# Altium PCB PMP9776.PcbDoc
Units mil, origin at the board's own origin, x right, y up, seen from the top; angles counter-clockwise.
Board outline 1968.5 x 590.55 mil, 2 copper layers (Top Layer, Bottom Layer), stack 62 mil thick; 59 components, 35 nets, 155 pads, 22 vias.
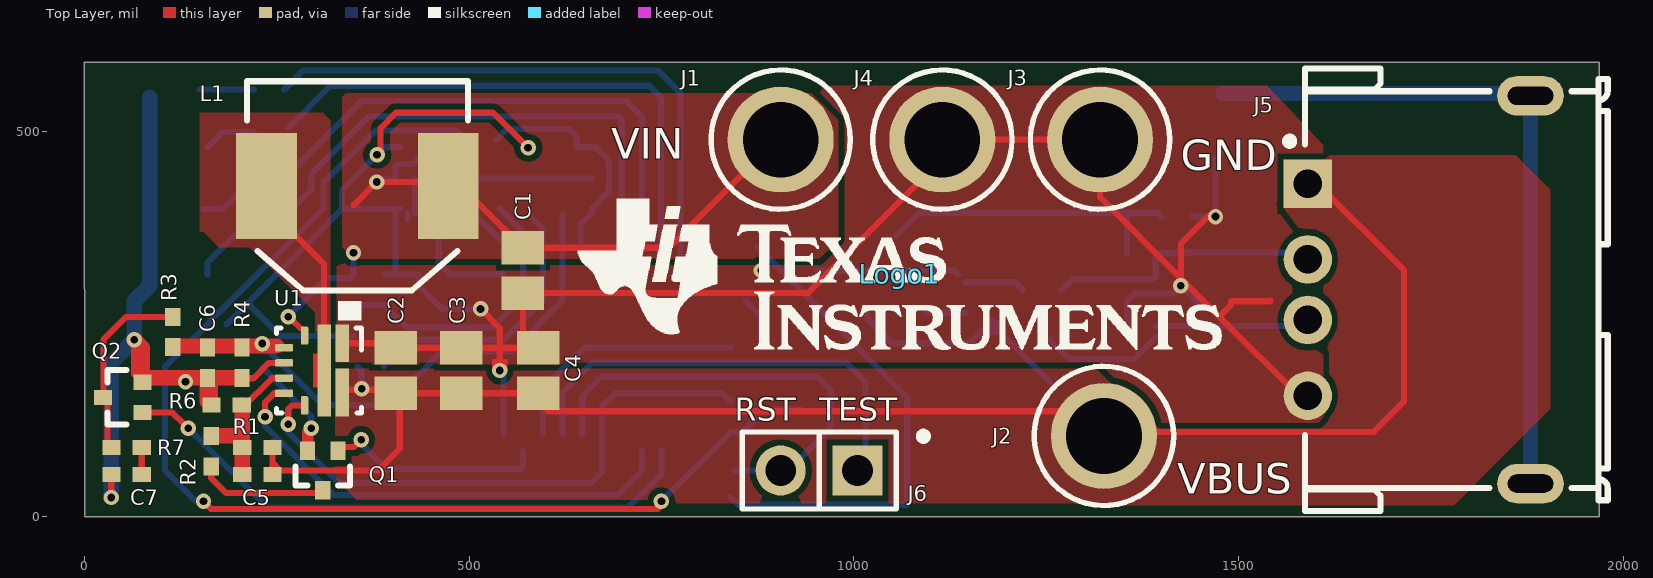
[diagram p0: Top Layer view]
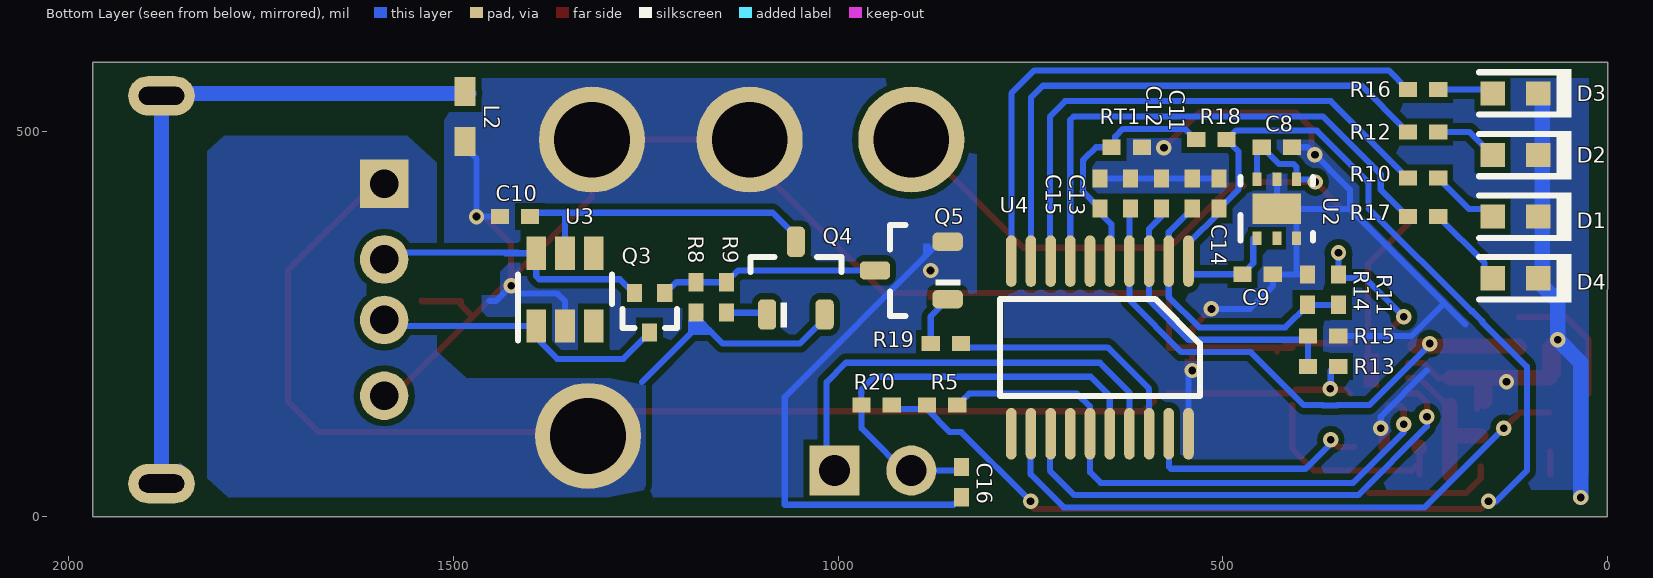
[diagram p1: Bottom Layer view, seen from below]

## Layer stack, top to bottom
Top Solder: solder mask 0.4, Solder Resist, Dk 3.5
Top Layer: signal copper 1.4
Dielectric1: core 59.2, FR-4, Dk 4.8
Bottom Layer: signal copper 1.4
Bottom Solder: solder mask 0.4, Solder Resist, Dk 3.5

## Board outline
0.55,0 1968.5,0 1968.5,590.55 0,590.55

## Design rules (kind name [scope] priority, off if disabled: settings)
AcuteAngle [All] p1: minimum=4.50000000000000E+0001 checktracksonly=FALSE
AssemblyTestPointUsage [All] p1: valid=2
Clearance "U1 Clearance" [InComponent('U1')] p1: gap=4
Clearance "U2 Clearance" [InComponent('U2')] p2: gap=4
Clearance Clearance_BoardEdge_MountingHoles [OnCopper and InComponentClass('Mounting Holes') vs IsKeepOut] p3: gap=3.94
Clearance Clearance_BoardEdge_Poly [OnCopper and InPoly vs IsKeepOut] p4: gap=10
Clearance Clearance_BoardEdge [OnCopper and Not InComponentClass('Logo') and not InComponentClass('FiducialMark') and not InRegion(1000,500,4000,800) vs IsKeepOut] p5: gap=30
Clearance [All] p6: gap=6
ComponentClearance ComponentClearance_SHUNT [InComponentClass('Shunt')] p1: gap=0 collisioncheckmode=3 verticalgap=0 showdistances=FALSE
ComponentClearance ComponentClearance_Logo [All] p2: gap=10 collisioncheckmode=3 verticalgap=10 showdistances=FALSE
ComponentClearance ComponentClearance_ScrewToNut [(HasFootprint('NY PMS 440 0025 PH')) vs (HasFootprint('Keystone_1902C'))] p3: gap=5 collisioncheckmode=3 verticalgap=10 showdistances=FALSE
ComponentClearance ComponentClearance_MountingHoles [InComponentClass('Mounting Holes')] p4: gap=250 collisioncheckmode=3 verticalgap=100000 showdistances=FALSE
ComponentClearance ComponentClearance_SmallPassives [HasFootprint('0201*') or HasFootprint('0402*') or HasFootprint('0508') or HasFootprint('0603*') or HasFootprint('0612') or HasFootprint('0805*') or HasFootprint('0815*') or HasFootprint('0830*') or HasFootprint('1206*') or HasFootprint('1210*') or HasFootprint('1808*') or HasFootprint('1812*') or HasFootprint('1825*') or HasFootprint('2010*') or HasFootprint('2220*') or HasFootprint('2225*') or HasFootprint('2512*') or HasFootprint('2728*') or HasFootprint('3518*') vs HasFootprint('0201*') or HasFootprint('0402*') or HasFootprint('0508') or HasFootprint('0603*') or HasFootprint('0612') or HasFootprint('0805*') or HasFootprint('0815*') or HasFootprint('0830*') or HasFootprint('1206*') or HasFootprint('1210*') or HasFootprint('1808*') or HasFootprint('1812*') or HasFootprint('1825*') or HasFootprint('2010*') or HasFootprint('2220*') or HasFootprint('2225*') or HasFootprint('2512*') or HasFootprint('2728*') or HasFootprint('3518*')] p5: gap=20 collisioncheckmode=3 verticalgap=10 showdistances=FALSE
ComponentClearance ComponentClearance_THtoSMT [IsThruComponent vs IsSMTComponent] p6 off: gap=10 collisioncheckmode=3 verticalgap=100000 showdistances=FALSE
ComponentClearance ComponentClearance_THtoTH [IsThruComponent vs IsThruComponent] p7: gap=10.11 collisioncheckmode=3 verticalgap=100000 showdistances=FALSE
ComponentClearance [All] p8: gap=10 collisioncheckmode=3 verticalgap=10 showdistances=FALSE
DiffPairsRouting [All] p1: maxlimit=100 minlimit=10 mostfreqgap=10 toplayer_minwidth=15 toplayer_maxwidth=15 toplayer_prefwidth=15 bottomlayer_minwidth=15 bottomlayer_maxwidth=15 bottomlayer_prefwidth=15 maxuncoupledlength=1000
FabricationTestPointUsage TestPointUsage [All] p1: valid=2 allowmultiple=FALSE
FabricationTestpoint Testpoint [All] p1: side=3 testpointundercomponent=TRUE minsize=40 maxsize=100 preferedsize=60 minholesize=0 maxholesize=40 preferedholesize=32 testpointgrid=1 allowsidetop=TRUE allowsidebottom=TRUE usegrid=TRUE gridtolerance=0.01
FanoutControl Fanout_LCC [IsLCC] p1: bgadir=Out bgaviamode=Centered fanoutstyle=Auto fanoutdirection=Alternating viagrid=1 // Fanout_LCC (Default Rule)
FanoutControl Fanout_BGA [IsBGA] p2: bgadir=Out bgaviamode=Centered fanoutstyle=Auto fanoutdirection=Alternating viagrid=1 // Fanout_BGA (Default Rule)
FanoutControl Fanout_Default [All] p4: bgadir=Out bgaviamode=Centered fanoutstyle=Auto fanoutdirection=Alternating viagrid=1 // Fanout_Default (Default Rule)
FanoutControl Fanout_Small [(CompPinCount < 5)] p5: bgadir=Out bgaviamode=Centered fanoutstyle=Auto fanoutdirection=OutThenIn viagrid=1 // Fanout_Small (Default Rule)
HoleSize [All] p1: absolutevalues=TRUE maxlimit=180 minlimit=8 maxpercent=80.000 minpercent=20.000
HoleToHoleClearance [All] p1: gap=1 allowstackedmicrovias=TRUE
MinimumAnnularRing MinimumAnnularRing_small [TouchesRoom('BGA_Room')] p1: minimumring=2.8
MinimumAnnularRing [All] p2: minimumring=5
MinimumSolderMaskSliver U2 [InComponent('U1')] p1: minsoldermaskwidth=3
MinimumSolderMaskSliver "SW PIN" [InNet('SW')] p2: minsoldermaskwidth=10
MinimumSolderMaskSliver U1 [InComponent('U2')] p3: minsoldermaskwidth=3
MinimumSolderMaskSliver MinimumSolderMaskSliver_Logo [InComponentClass('Logo') vs InComponentClass('Logo')] p4: minsoldermaskwidth=0.7
MinimumSolderMaskSliver [All] p5: minsoldermaskwidth=4
PlaneClearance [All] p1: clearance=10
PlaneConnect [All] p1: planeconnectstyle=Direct reliefexpansion=10 reliefentries=4 reliefconductorwidth=10 reliefairgap=10
PolygonConnect PolygonConnect-TH-Relief [IsPoly vs (IsThruPin)  And Not (InComponent('U3'))  And Not (InComponent('U4'))] p1: connectstyle=Direct reliefconductorwidth=20 reliefentries=4 polygonreliefangle="90 Angle" airgapwidth=10
PolygonConnect PolygonConnect-DirectConn [All] p2: connectstyle=Direct reliefconductorwidth=10 reliefentries=4 polygonreliefangle="90 Angle" airgapwidth=10
RoutingVias [All] p1: holewidth=10 width=22 viastyle="Through Hole" minholewidth=4 minwidth=10 maxholewidth=50 maxwidth=100
SMDToCorner [All] p1: distance=0
SilkToSilkClearance [All] p1: silktosilkclearance=3
SilkToSolderMaskClearance [IsPad] p1: minsilkscreentomaskgap=5 clearancetoexposedcopper=TRUE
SolderMaskExpansion [All] p1: expansion=1
UnpouredPolygon [All] p1: allowunpoured=FALSE
Width [All] p1: maxlimit=100 minlimit=6 preferedwidth=10 checkconnectedcopper=TRUE
13 further rules are at their usual default settings.

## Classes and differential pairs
component class PMP9776_Hardware: !PCB1 Logo1
component class Header: J6
component class Logo: Logo1

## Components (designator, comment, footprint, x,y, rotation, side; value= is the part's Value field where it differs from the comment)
C1 "GRM21BR61A226ME44" 0805L 570,320 r270 top
C2 "GRM21BR61A226ME44" 0805L 405,190 r90 top
C3 "GRM21BR61A226ME44" 0805L 490,190 r90 top
C4 "GRM21BR61A226ME44" 0805L 590,190 r90 top
C5 "GRM1555C1H100JA01D" 0402L 225,55 r180 top
C6 "GRM155R71H103KA88D" 0402L 160,200 r270 top
C7 "GRM155R71E104KE14D" 0402L 55,55 r180 top
C8 "GRM155R61A105KE15D" 0402L 430,480 r180 bottom
C9 "GRM155R61A105KE15D" 0402L 455,315 r180 bottom
C10 "GRM155R61A105KE15D" 0402L 1420,390 r0 bottom
C11 "GRM155R71H102KA01D" 0402L 540,420 r270 bottom
C12 "GRM155R71H102KA01D" 0402L 580,420 r270 bottom
C13 "GRM155R71H102KA01D" 0402L 620,420 r270 bottom
C14 "GRM155R61A105KE15D" 0402L 505,420 r90 bottom
C15 "GRM155R71H102KA01D" 0402L 660,420 r270 bottom
C16 "GRM155R71H102KA01D" 0402L 840,45 r90 bottom
D1 "HSMC-C190" HSMx-C190_Red 120,390 r180 bottom
D2 "HSMC-C190" HSMx-C190_Red 120,470 r180 bottom
D3 "HSMC-C190" HSMx-C190_Red 120,550 r180 bottom
D4 "HSMC-C190" HSMx-C190_Red 120,310 r180 bottom
J1 "Suggest using a net name here" Keystone1502-2 905,490 r0 top
J2 "Suggest using a net name here" Keystone1502-2 1325,105 r0 top
J3 "Suggest using a net name here" Keystone1502-2 1320,490 r0 top
J4 "Suggest using a net name here" Keystone1502-2 1115,490 r0 top
J5 "614 104 150 121" WURTH_614104150121 1590,295 r90 top
J6 "TSW-102-07-G-S" TSW-102-07-G-S 955,60 r180 top
L1 "FDSD0630-H-1R0M" FDSD0630 355,430 r180 top
L2 "74279266A" WE-CBF_0603 1485,520 r90 bottom
Logo1 "Texas Instruments" TI_Stacked_Overlay_Small 1060,315 r0 top
Q1 "SI1012CR-T1-GE3-ND" SOT-416 310,60 r270 top
Q2 "SI1012CR-T1-GE3-ND" SOT-416 50,155 r180 top
Q3 "SI1012CR-T1-GE3-ND" SOT-416 1245,265 r270 bottom
Q4 "MMBT3906" SOT-23 1055,310 r90 bottom
Q5 "MMBT3904" SOT-23 905,320 r0 bottom
R1 "CRCW0402806KFKED" 0402L 225,90 r0 top
R2 "CRCW040210M0FKED" 0402L 165,85 r90 top
R3 "CRCW040256K2FKED" 0402L 115,240 r270 top
R4 "CRCW0402124KFKED" 0402L 205,200 r90 top
R5 "CRCW0402511KFKED" 0402L 865,145 r180 bottom
R6 "CRCW0402261KFKED" 0402L 185,145 r0 top
R7 "CRCW0402100RFKED" 0402L 55,90 r180 top
R8 "CRCW0402100KFKED" 0402L 1185,285 r270 bottom
R9 "CRCW0402100KFKED" 0402L 1145,285 r90 bottom
R10 "CRCW04021K00FKED" 0402L 240,440 r180 bottom
R11 "CRCW04022M00FKED" 0402L 350,295 r270 bottom
R12 "CRCW04021K00FKED" 0402L 240,500 r180 bottom
R13 "CRCW04022M00FKED" 0402L 370,195 r0 bottom
R14 "CRCW0402511KFKED" 0402L 390,295 r270 bottom
R15 "CRCW0402511KFKED" 0402L 370,235 r0 bottom
R16 "CRCW04021K00FKED" 0402L 240,555 r180 bottom
R17 "CRCW04021K00FKED" 0402L 240,390 r180 bottom
R18 "CRCW04022M00FKED" 0402L 515,490 r180 bottom
R19 "CRCW0402100KFKED" 0402L 860,225 r180 bottom
R20 "CRCW0402100KFKED" 0402L 950,145 r180 bottom
RT1 "NCP15WM474J03RC" 0402L 625,480 r0 bottom
U1 "TPS61236RWLR" RWL0009A 305,190 r270 top
U2 "TPS78230DRVR" DRV0006A 430,400 r90 bottom
U3 "TPS2514ADBV" DBV0006A_N 1355,295 r90 bottom
U4 "MSP430G2332IPW20" PW0020A_N 660,220 r270 bottom

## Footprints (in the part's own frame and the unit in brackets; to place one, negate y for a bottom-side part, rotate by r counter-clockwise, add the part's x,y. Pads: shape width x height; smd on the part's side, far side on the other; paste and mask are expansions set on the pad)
0402L [mm] "0402 from SM-752 data"
  rect 0.6x0.5 smd: 1(-0.5,0) 2(0.5,0)
  body extent -0.55,-0.3 0.55,0.3, height 0.6
0805L [mm] "0805 from SM-752 data"
  rect 1.1x1.4 smd: 1(-0.75,0) 2(0.75,0)
  body extent -1.1,-0.72 1.1,0.72, height 1.1
DBV0006A_N [mm] "SOT23, 6-Leads, Body 2.9x1.6mm, Pitch 0.95mm, Lead Span 2.8mm, IPC Medium Density"
  rect 1.1x0.65 smd: 1(-1.2,0.95) 2(-1.2,0) 3(-1.2,-0.95) 4(1.2,-0.95) 5(1.2,0) 6(1.2,0.95)
  silkscreen extent -1.68,-1.55 0.5,1.55, body extent -1.42,-1.46 1.42,1.46, height 1.11
DRV0006A [mm] "SON, 6-Leads, Body 2x2mm, Pitch 0.65mm, Thermal Pad 1.6x1mm, TI Recommended"
  rect 0.45x0.3 smd: 1(-0.975,0.65) 2(-0.975,0) 3(-0.975,-0.65) 4(0.975,-0.65) 5(0.975,0) 6(0.975,0.65)
  rect 1x1.6 smd paste-0.5: 7(0,0)
  silkscreen extent -1.05,-1.2 1.05,1.2, body extent -1.05,-1.05 1.05,1.05, height 0.81
FDSD0630 [mm] "SMD, 2-Leads, Body 6.6x7mm"
  rect 2x3.5 smd: 1(-3,0) 2(3,0)
  silkscreen extent -3.65,-3.45 3.65,3.45, body extent -3.65,-3.45 3.65,3.45, height 3
HSMx-C190_Red [mm] "SMD, 2-Leads, Body 0.8x1.6mm"
  rect 0.8x0.8 smd: 1(-0.75,0) 2(0.75,0)
  silkscreen extent -1.2,-0.8 1.85,0.8, body extent -0.85,-0.45 0.85,0.45, height 0.9
Keystone1502-2 [mm] "Double Turret"
  round 3.5 hole 2.5: 1(0,0)
  silkscreen extent -2.3,-2.3 2.3,2.3, body extent -1.6,-1.6 1.59,1.6, height 5.62
PW0020A_N [mm] "TSOP, 20-Leads, Body 6.5x4.4mm, Pitch 0.65mm, IPC Medium Density"
  oval 1.7x0.35 smd: 1(-2.85,2.925) 2(-2.85,2.275) 3(-2.85,1.625) 4(-2.85,0.975) 5(-2.85,0.325) 6(-2.85,-0.325) 7(-2.85,-0.975) 8(-2.85,-1.625) 9(-2.85,-2.275) 10(-2.85,-2.925) 11(2.85,-2.925) 12(2.85,-2.275) 13(2.85,-1.625) 14(2.85,-0.975) 15(2.85,-0.325) 16(2.85,0.325) 17(2.85,0.975) 18(2.85,1.625) 19(2.85,2.275) 20(2.85,2.925)
  silkscreen extent -1.6,-3.3 1.6,3.3, body extent -3.21,-3.25 3.21,3.25, height 0.99
RWL0009A [mm] "VQFN, 2.5x2.5mm"
  rect 1.24x0.44 smd paste-0.3 mask-0.07: 1(-0.9,0.77)
  rect 3.04x0.44 smd paste-0.5 mask-0.07: 2(0,0.17)
  rrect40% 0.6x0.25 smd: 3(-1.15,-0.475) 8(1.15,-0.475)
  rrect40% 0.25x0.6 smd: 4(-0.75,-1.15) 5(-0.25,-1.15) 6(0.25,-1.15) 7(0.75,-1.15)
  rect 1.59x0.44 smd paste-0.3 mask-0.07: 9(0.725,0.77)
  Top Layer region: -0.557,-0.2 0.557,-0.2 0.557,0.32 -0.557,0.32
  silkscreen extent -1.4,-1.4 1.4,1.4, body extent -1.3,-1.3 1.3,1.3, height 1.05
SOT-23 [mm] "SOT23, 3-Leads, Body 2.9x1.3mm, Pitch 0.95mm, Lead Span 2.5mm, IPC Medium Density"
  rrect50% 1x0.6 smd: 1(-1.2,0.95) 2(-1.2,-0.95) 3(1.2,0)
  silkscreen extent -1.62,-1.5 0.7,1.5, body extent -1.16,-1.45 1.21,1.45, height 1
SOT-416 [mm] "NXP recommended footprint."
  rect 0.6x0.5 smd: 1(-0.65,0.5) 2(-0.65,-0.5) 3(0.65,0)
  silkscreen extent -0.13,-0.9 0.5,0.9, body extent -0.8,-0.9 0.8,0.9, height 0.82
TI_Stacked_Overlay_Small [mil]
  silkscreen extent -418,-98 418,98
TSW-102-07-G-S [mm] "Samtec 100mil, 1x2, 230 mil above insulator"
  rect 1.65x1.65 hole 1.016 mask+0: 1(-1.27,0)
  round 1.65 hole 1.016 mask+0: 2(1.27,0)
  silkscreen extent -3.57,-1.27 2.54,1.27, body extent -2.54,-1.27 2.54,1.27, height 8.38
WE-CBF_0603 [mm] "WE_SMT-0603"
  rect 0.95x0.7 smd: 1(-0.825,0) 2(0.825,0)
  body extent -0.9,-0.5 0.9,0.5, height 1
WURTH_614104150121 [mm] "USB2.0 A, TH"
  rect 1.6x1.6 hole 0.94: 1(3.5,0)
  round 1.6 hole 0.94: 2(1,0) 3(-1,0) 4(-3.5,0)
  oval 1.3x2.2 hole 0.6 slot 1.5 at 90 deg: 5(-6.4,-7.35) 6(6.4,-7.35)
  silkscreen extent -7.3,-9.9 7.3,0.72, body extent -7.3,-9.9 7.3,0.1, height 6.93

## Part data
C1 C2 C3 C4: "CAP, CERM, 22uF, 10V, +/-20%, X5R, 0805"
C5: "CAP, CERM, 10 pF, 50 V, +/- 5%, C0G/NP0, 0402"
C6: "CAP, CERM, 0.01 µF, 50 V, +/- 10%, X7R, 0402"
C7: "CAP, CERM, 0.1 µF, 25 V, +/- 10%, X7R, 0402"
C8 C9 C10 C14: "CAP, CERM, 1 µF, 10 V, +/- 10%, X5R, 0402"
C11 C12 C13 C15 C16: "CAP, CERM, 1000 pF, 50 V, +/- 10%, X7R, 0402"
D1 D2 D3 D4: "LED, Red, SMD"
J1 J2 J3 J4: library part 1502-2, "Terminal, Turret, TH, Double"
J5: "Connector, Receptacle, USB Type A, R/A, Bottom Mount TH"
J6: "Header, 100mil, 2x1, Gold, TH"
L1: "Inductor, Shielded, Metal Composite, 1 µH, 9.4 A, 0.009 ohm, SMD"
L2: "Ferrite Bead, 1000 ohm @ 100 MHz, 0.2 A, 0603"
Logo1: library part TI_Logo, "Texas Instrument Corporate Signature"
Q1 Q2 Q3: "MOSFET, N/P-CH, 20 V, 0.63 A, SOT-416"
Q4: library part "MMBT3906, Fairchild Semiconductor", "Transistor, PNP, 40 V, 0.2 A, SOT-23"
Q5: library part "MMBT3904, Fairchild Semiconductor", "Transistor, NPN, 40 V, 0.2 A, SOT-23"
R1: "RES, 806 k, 1%, 0.063 W, 0402"
R2: "RES, 10.0 M, 1%, 0.063 W, 0402"
R3: "RES, 56.2 k, 1%, 0.063 W, 0402"
R4: "RES, 124 k, 1%, 0.063 W, 0402"
R5 R14 R15: "RES, 511 k, 1%, 0.063 W, 0402"
R6: "RES, 261 k, 1%, 0.063 W, 0402"
R7: "RES, 100, 1%, 0.063 W, 0402"
R8 R9 R19 R20: "RES, 100 k, 1%, 0.063 W, 0402"
R10 R12 R16 R17: "RES, 1.00 k, 1%, 0.063 W, 0402"
R11 R13 R18: "RES, 2.00 M, 1%, 0.063 W, 0402"
RT1: "Thermistor NTC, 470k ohm, 5%, 0402"
U1: "7-A Synchronous Boost Converter with Programmable Output Current Limit, RWL0009A"
U2: "Single Output LDO, 150 mA, Fixed 3 V Output, 2.2 to 5.5 V Input, with 0.5 uA Quiescent Current, 6-pin SON (DRV), -40 to 125 degC, Green (RoHS & no Sb/Br)"
U3: "USB Dedicated Charging Port Controller, DBV0006A"
U4: "16 MHz Mixed Signal Microcontroller with 4 KB Flash, 256 B SRAM and 16 GPIOs, 20-pin SOP (PW), Green (RoHS & no Sb/Br)"

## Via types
v1: diameter 20, hole 10, Top Layer to Bottom Layer, 22 vias

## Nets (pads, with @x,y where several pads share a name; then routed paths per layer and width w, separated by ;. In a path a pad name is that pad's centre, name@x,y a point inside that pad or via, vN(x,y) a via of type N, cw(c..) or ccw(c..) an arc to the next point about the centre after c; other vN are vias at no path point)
3V: C9.1 C14.1 R5.1 R18.2 R20.2 U2.1 U4.1 | length 1878.8
  Top Layer w8: v1(155,20) 165,10 745,10 v1@750,15
  Bottom Layer w8: v1(155,20) 145,20 105,60 105,195 163,253 163,254.11 175.89,267 177,267 311,401 311,434.68 378.16,501.84 483.16,501.84 R18.2@490,495 ; U2.1@460.59,361.61 460.59,329.41 C9.1@475,315 ; C9.1 C9.1@475,315 ; R18.2@490,490 R18.2 480,474.69 480,425 C14.1@500,405 ; C14.1@505,395 544.84,355.16 U4.1 ; U4.1@545,315 C9.1@475,315 ; v1(750,20) 840,110 855,110 R5.1@885,140 ; R5.1@881.11,140 R5.1@885,140 ; R20.2@930,140 R5.1@885,140
CC: C6.1 C13.2 R3.2 R4.2 U1.4 U4.4 | length 868.9
  Top Layer w8: R3.2@115,219.69 R4.2 U1.4@254.69,219.69
  Top Layer w20: R3.2 116.53,221.84 U1.4@250,221.84
  Bottom Layer w8: v1@230,225 310,145 350.81,145 351.42,144.38 369.65,144.38 370.27,145 395,145 464,214 554,214 621.61,281.61 U4.4 C13.2@621.61,393.39
  other v1: 231.32,224.96
D+: J5.3 Q3.3 U3.1 | length 382
  Bottom Layer w8: Q3.3 1279.41,205 1365,205 U3.1@1395,235 ; U3.1 J5.3@1597.76,247.76
D-: J5.2 Q3.2 U3.6 | length 377.1
  Bottom Layer w8: Q3.2@1270,295 1283.59,308.59 1388.59,308.59 1392.4,312.4 U3.6 1432.76,342.24 ; 1416.5,343.5 1580.87,343.5 J5.2
EN: U1.7 U4.13 | length 626.1
  Top Layer w8: v1(235,130) 235,148.49 246.99,160.47 U1.7
  Bottom Layer w8: v1(235,130) 235,117.37 324.37,28 693,28 725,60 U4.13@725,85
GND: C1.2 C2.2 C3.2 C4.2 C6.2 C7.2 C8.2 C9.2 C10.2 C11.1 C12.1 C13.1 C14.2 C15.1 C16.1 D1.2 D2.2 D3.2 D4.2 J3.1 J4.1 J5.4 L2.1 Q1.2 Q2.2 Q5.2 R4.1 R6.1 R14.1 R15.1 RT1.1 U1.1 U1.5 U2.3 U2.5 U2.7 U3.2 U4.20 | length 5300
  Top Layer w8: v1(35,25) C7.2@35,55 ; v1(65,230) 65,185 Q2.2@70,180 ; Q2.2 160,174.68 C6.2@160.32,174.68 ; R6.1@170,140 170,180 220,180 239.84,199.84 U1.5 ; U1.1 C2.2@419.57,225.43 ; v1(380.52,470.54) 384.46,470.54 v1@385,470 ; v1@385,473.8 385,505 405,525 530.92,525 531.23,524.69 531.57,524.69 v1(576.77,479.49) ; C2.2@410,219.53 C2.2@430,219.53 ; C2.2@430,215 C2.2@430,219.53 ; v1(515,270) 540,245 540,219.53 ; v1(540,190) 540,219.53 ; C4.2@569.53,219.53 540,219.53 ; C4.2@570,219.53 C1.2@570,290 ; C1.2 880,290.47 ; 880,285 880,290.47 ; 940,290 940.47,290.47 ; J4.1 J3.1@1290,490 ; J4.1@1125,475 940.47,290.47 ; J3.1 1320,415 1425,310 ; v1(1425,300) 1425,310 ; v1(1470,390) 1460,390 1425,355 1425,310 ; 1541.48,280.52 1540.52,280.52 1540,280 1490,280 1490,275 1475,260 ; J5.4@1580,155 1475,260 ; C2.2@430,219.53 C3.2 540,219.53 ; 880,290.47 940.47,290.47 ; 1425,310 1475,260
  Top Layer w15: Q1.2@290.32,90.59 290.32,110.32 v1(295,115)
  Top Layer w20: v1(65,230) 75.32,219.68 75.32,180.32 R4.1 ; R6.1@160,150 160,174.68 C6.2
  Bottom Layer w8: D4.2@90,315 D4.2@90.47,315.47 ; 185,250 335,400 ; 215,275 255,235 R15.1@350,235 ; 235,190 295,130 v1(295,115) ; R14.1 C9.2@430,314.68 ; 404.41,315.59 U2.3 U2.7@404.41,394.41 ; U2.7@410,400 335,400 ; C8.2 390,480 335,425 335,400 ; U2.7@420,386.38 U2.7@420,395 ; C9.2@430,315 C9.2@430,314.68 ; U2.7@430,395 U2.7 U2.5 ; C9.2@435,310 430.32,314.68 C9.2@430,314.68 ; C9.2 435.31,299.69 465,270 v1(515,270) ; C14.2 C12.1 C15.1@659.69,439.69 ; v1(540,190) 544.84,185.16 U4.20 ; C16.1 849.8,15.52 1069.48,15.52 ; Q5.2@875,350 1069.48,155.52 ; 1070,16.04 1069.48,15.52 ; 1070,155 1069.48,155.52 ; U3.2 1355,280 1365,290 1415,290 v1(1425,300) 1444.68,280.32 1453.19,280.32 ; C10.2@1440,390 v1(1470,390) 1470,465 L2.1@1480,475 ; 1069.48,15.52 1069.48,155.52
  Bottom Layer w20: v1(35,25) 35,200 v1(65,230) 65,280 85,300 D3.2@85,545
  other v1: 131.54,175.19 880,320
INACT: R5.2 U1.8 U4.15 | length 755.8
  Top Layer w8: v1(265,120) 265,139.45 270.28,144.72 U1.8
  Bottom Layer w8: v1(265,120) 265,110 330,45 ; 331,44 659,44 672.8,57.8 U4.15 672.8,142.8 690,160 830,160 R5.2@840,150
LED: R17.1 U4.7 | length 682.1
  Bottom Layer w8: R17.1@265,395 295,425 295,445 370,520 694,520 698.39,515.61 U4.7
NetC5_2: C5.2 R1.1 R2.2 R6.2 U1.6 | length 206.8
  Top Layer w8: R6.2@203.89,140 R6.2@205.31,141.43 ; R6.2@205.32,145.32 R6.2@205.32,141.43 ; U1.6 244.04,180.16 R6.2@205.32,141.43
  Top Layer w20: R2.2@165,105 205.31,105 ; R6.2@205,145 205.31,144.69 205.31,141.43 205.31,105 ; C5.2 205.31,105
NetC7_1: C7.1 R7.1 | length 29.7
  Top Layer w8: C7.1 R7.1@74.68,84.68
NetC10_1: C10.1 Q4.3 U3.5 | length 412.3
  Bottom Layer w8: Q4.3@1055,365 1085,395 1355,395 ; U3.5 1355,395 ; C10.1@1400,390 1395,395 1355,395
NetC11_2: C11.2 R11.2 R14.2 U4.2 | length 376
  Bottom Layer w8: R11.2@350.31,275.31 R14.2 ; R14.2@390,275 419,246 531,246 570.43,285.43 U4.2 570.43,369.88 C11.2
NetC12_2: C12.2 R13.2 R15.2 U4.3 | length 377.5
  Bottom Layer w8: R13.2 R15.2@389.69,234.69 ; R15.2@395,230 545,230 596.02,281.02 U4.3 596.02,373.98 C12.2@580,390
NetC15_2: C15.2 R18.1 RT1.2 U4.5 | length 295.3
  Bottom Layer w8: R18.1 536,490 550,504 630,504 640,494 RT1.2@640,480 ; RT1.2 665,480 680,465 ; U4.5@645,355 645,380 660,395 C15.2 681.84,422.16 ; 681.84,421.84 681.84,422.16 ; 681.84,463.16 681.84,422.16 ; 682.39,422.7 681.84,422.16
NetD1_1: D1.1 R10.2 | length 81.9
  Bottom Layer w8: D1.1@155,400 180.31,400 R10.2
NetD2_1: D2.1 R12.2 | length 68.6
  Bottom Layer w8: D2.1@160,480 180,500 R12.2
NetD3_1: D3.1 R16.2 | length 70.3
  Bottom Layer w8: D3.1@150,555 R16.2
NetD4_1: D4.1 R17.2 | length 100
  Bottom Layer w8: D4.1@160,315 160,329.69 R17.2
NetJ5_5: J5.5 J5.6 L2.2 | length 1292.4
  Bottom Layer w8: L2.2 1852.48,552.48 J5.6@1855,555 ; J5.5@1855,65 J5.5@1870,50
  Bottom Layer w20: L2.2@1480,550 1868.74,550 1879.37,539.37 J5.5
NetL1_2: L1.2 U1.2 | length 211.4
  Top Layer w8: L1.2@260,380 311.69,328.31 U1.2
NetQ1_3: Q1.3 R2.1 | length 168.2
  Top Layer w8: R2.1 165,50 184,31 Q1.3@310,31
NetQ2_3: Q2.3 R3.1 R7.2 | length 242
  Top Layer w8: Q2.3@25,160 25,230 54.68,259.68 R3.1 ; R7.2@30.31,90 Q2.3@30.31,159.69
NetQ4_1: Q4.1 R9.1 | length 50.1
  Bottom Layer w8: Q4.1@1095,265 1144.68,265 R9.1
NetQ5_1: Q5.1 R19.1 | length 63.2
  Bottom Layer w8: Q5.1@860,280 879.68,260.32 R19.1
NetR10_1: R10.1 U4.8 | length 690
  Bottom Layer w8: R10.1 359.68,540 705,540 725,520 U4.8@725,345
NetR12_1: R12.1 U4.9 | length 726
  Bottom Layer w8: R12.1@265,505 320,560 734,560 749.57,544.43 U4.9
NetR16_1: R16.1 U4.10 | length 758.1
  Bottom Layer w8: R16.1 284.68,580 745,580 775,550 U4.10@775,330
NetR19_2: R19.2 U4.18 | length 324.6
  Bottom Layer w8: U4.18 596.02,166.02 650,220 R19.2@840,220
R\S\T\: C16.2 J6.2 R20.1 U4.16 | length 586.3
  Bottom Layer w8: U4.16 647.2,157.2 671.84,181.84 953.16,181.84 970,165 970,160 ; C16.2@845,60 J6.2 ; J6.2@905,50 969.69,114.69 969.69,154.69 970,155
TEST: J6.1 U4.17 | length 578.5
  Bottom Layer w8: U4.17 621.61,161.61 660,200 990,200 1015,175 J6.1@1015,70
VBAT: C1.1 C8.1 J1.1 L1.1 R11.1 U1.3 U2.4 U2.6 | length 904.2
  Top Layer w8: v1(265,260) U1.3@286.3,240.28 ; 350,405 v1(380,435) L1.1@455,435 ; L1.1 L1.1@495,430 ; L1.1@485,425 494.53,425 C1.1 ; C1.1@570,350 C1.1 ; J1.1@885,475 759.53,349.53 C1.1
  Bottom Layer w8: v1(265,260) 315,310 R11.1@345,310 ; R11.1@349.95,313.9 v1(349.95,343.13) ; v1@383.39,438.39 U2.4 404.41,454.41 408.16,458.16 427.1,458.16 443.94,475 C8.1@445,475 ; U2.6 C8.1@455.59,474.41
VBUS: C2.1 C3.1 C4.1 C5.1 J2.1 J5.1 Q4.2 R1.2 R8.2 R13.1 U1.9 | length 2346.9
  Top Layer w8: C5.1 244.68,70 ; R1.2@244.68,94.68 244.68,89.68 244.68,70 ; U1.9@335,160 340,165 405.47,165 410,160.47 C3.1 C4.1@570,160.47 ; C2.1@410,145 410,88.56 381.44,60 254.68,60 244.68,70 ; C4.1@590,150 603,137 1328,137 1355,110 1675,110 1715,150 1715,320 J5.1@1605,430
  Top Layer w20: R1.2@244.68,89.68 R1.2@245,90
  Bottom Layer w8: R13.1@355,195 360,190 360,170 360.54,169.46 v1(360.54,166.38) ; Q4.2 1017.6,257.4 1050,225 1150,225 1165,240 ; 1172.5,242.5 1167.5,242.5 ; R8.2@1180,255 1167.5,242.5 ; 1255,175 1190,240 1165,240 ; 1165,240 1167.5,242.5
VCOM: Q1.1 U4.19 | length 277
  Top Layer w8: Q1.1@329.69,90.59 350.59,90.59 v1@355,95
  Bottom Layer w8: v1(360,100) 360,95 392.67,62.33 567.67,62.33 570,64.66 U4.19@570,85
VCUR: Q2.1 U4.12 | length 766.2
  Top Layer w8: Q2.1 114.69,135.31 v1@130,120
  Bottom Layer w8: v1(135,115) 238,12 707,12 750,55 U4.12@750,85
VINT: Q3.1 Q5.3 R8.1 R9.2 | length 263.5
  Bottom Layer w8: Q5.3 1130,320 1135,315 ; R9.2@1145.32,304.68 R8.1 1210.32,304.68 Q3.1@1220,295
pads on no net: U2.2 U3.3 U3.4 U4.6 U4.11 U4.14

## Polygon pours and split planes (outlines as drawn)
GND on Bottom Layer "Bottom Layer-No Net 2" (solid, remove dead copper, pour order 12): 832.7,570 1477.21,570 1512.14,515 1512.14,85 1483.56,40 1474.04,25 1000.97,25 842.22,25 820,60 820,550 832.7,570
GND on Bottom Layer "Bottom Layer-No Net 1" (solid, remove dead copper, pour order 11): 25,570 775,570 785,545 785,65 773,35 33,35 25,55 25,570
VBUS on Bottom Layer "Bottom Layer-No Net" (solid, pour order 10): 1189.64,180 1189.64,40 1206.23,25 1792.35,25 1820,50 1820,475 1797.88,495 1560.12,495 1521.41,460 1521.41,215 1515.88,210 1482.7,180 1455.06,180 1189.64,180
VBUS on Top Layer "Top Layer-No Net 3" (solid, remove dead copper, pour order 17): 1300,145 1300,15 1780,15 1835,70 1905,140 1905,255 1905,425 1860,470 1375,470 1345,440 1290,385 1290,20
GND on Top Layer "Top Layer-No Net 2" (solid, remove dead copper, pour order 16): 325,198.07 1314.21,198.07 1353,156.7 1401.49,105 1610,105 1610,482.44 1537.26,560 325,560 325,198.07
VBUS on Top Layer "Top Layer-No Net 1" (solid, remove dead copper, pour order 15): 326.77,192.22 1314.99,192.22 1347.11,160.1 1347.11,51.23 1313.62,17.74 358.01,17.74 327.14,48.6 326.44,49.3 326.44,145.93 326.44,191.8 327.13,192.48
VBAT on Top Layer "Top Layer-No Net" (solid, pour order 13): 340,550 945,550 980,515 980,360 955,335 350,335 335,350 335,545 340,550
NetL1_2 on Top Layer "Top Overlay-No Net" (solid, pour order 14): 150,525 310,525 320,515 320,245 315,240 300,240 300,265 285,280 215,350 175,350 155,370 150,370 150,525

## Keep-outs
Keep-Out Layer:
  text ".Layer_Name" at 577,-858.49 h60

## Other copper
Top Layer:
  rectangle net GND: 530,190 550,205
  text ".Layer_Name" at 577,-858.49 h60
Bottom Layer:
  rectangle net VBUS: 1175,240 1195,255
  rectangle net GND: 880,340 890,355
  text ".Layer_Name" at 577,-858.49 h60

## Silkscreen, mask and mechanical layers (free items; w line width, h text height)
Top Overlay:
  rectangle: 330,255 360,280
  text "VIN" at 685,465 h40
  text "GND" at 1425,450 h40
  text "RST" at 845,125 h30
  text "TEST" at 955,125 h30
  text "VBUS" at 1420,30 h40
  text ".Layer_Name" at 577,-858.49 h60
Bottom Overlay:
  text ".Layer_Name" at 577,-858.49 h60
Top Paste:
  text ".Layer_Name" at 577,-858.49 h60
Bottom Paste:
  text ".Layer_Name" at 577,-858.49 h60
Top Solder:
  text ".Layer_Name" at 577,-858.49 h60
  text ".Layer_Name" at 577,-858.49 h60
Bottom Solder:
  text ".Layer_Name" at 577,-858.49 h60
Drill Guide:
  text ".Layer_Name" at 577,-858.49 h60
M1 Board Outline:
  lines w7.87: 0,0 0,590.55 ; 0.55,0 1968.5,0 1968.5,590.55 0.55,590.55
  text ".Layer_Name" at 577,-858.49 h60
M2 Board Dimensions:
  rectangle: 125,-410.5 500,-285.5
  rectangle: 0,-285.5 125,-160.5
  lines w7: 0,-285.5 1000,-285.5 ; 125,-410.5 125,-160.5 ; 250,-410.5 250,-160.5 ; 500,-410.5 500,-160.5 ; 750,-410.5 750,-160.5 ; 0,-410.5 0,-160.5 1000,-160.5 1000,-410.5 0,-410.5
  text ".Layer_Name" at 577,-858.49 h60
M3 3D STEP Top:
  text ".Layer_Name" at 577,-858.49 h60
M4 3D STEP Bottom:
  text ".Layer_Name" at 577,-858.49 h60
M5 Assembly Top:
  lines w10: -292,-930.17 6308,-930.17 ; -292,-726.83 6310,-726.83 ; -292,-523.5 -292,-1133.5 3713,-1133.5 6310,-1133.5 6310,-523.5 -291.5,-523.5 -291.5,-1133.5 1284,-1133.5 ; 2173,-1133.5 2173,-523.5 ; 3440,-726.83 3440,-523.5 ; 4280,-726.83 4280,-523.5 ; 4902,-1140 4902,-937.17
  text "COMPONENTS MARKED 'DNP' SHOULD NOT BE POPULATED." at 1153.5,-318.5 h60
  text "ASSEMBLY VARIANT:" at 1153,-434 h60
  text ".VariantName" at 2189,-434 h60
  text "PCB VIEWED FROM TOP SIDE" at -228.5,-655.67 h60
  text "BOARD #:" at 2248,-655.67 h60
  text ".PRJ_Number" at 2793.5,-655.67 h60
  text "REV:" at 3638,-655.67 h60
  text ".PCB_Rev" at 3929.5,-655.67 h60
  text "SVN REV:" at 4476,-655.67 h60
  text ".VersionControl_RevNumber" at 4982,-655.67 h60
  text "IGNORE ->" at -228.5,-858.49 h60
  text "PLOT NAME =" at -228.5,-1064.34 h60
  text ".plot_File_Name" at 577,-1064.34 h60
  text "GENERATED    :" at 2250,-1064.34 h60
  text ".Print_Date" at 3119.5,-1064.34 h60
  text ".Print_Time" at 3848.5,-1064.34 h60
  text "TEXAS INSTRUMENTS" at 5113,-1064.34 h60
M6 Assembly Bottom:
  lines w10: -292.5,-727.33 6309.5,-727.33 ; -290.5,-930.67 6309.5,-930.67 ; 1115.5,-1140.5 1115.5,-937.67 ; 1737.5,-727.33 1737.5,-524 ; 2577.5,-727.33 2577.5,-524 ; 3844.5,-1134 3844.5,-524 ; 4733.5,-1134 6309,-1134 6309,-524 -292.5,-524 -292.5,-1134 2304.5,-1134 6309.5,-1134 6309.5,-524
  text "COMPONENTS MARKED 'DNP' SHOULD NOT BE POPULATED." at 6102,-318 h60
  text ".VariantName" at 5058,-434 h60
  text "ASSEMBLY VARIANT:" at 6097,-434 h60
  text ".VersionControl_RevNumber" at 1035.5,-656.17 h60
  text "SVN REV:" at 1541.5,-656.17 h60
  text ".PCB_Rev" at 2088,-656.17 h60
  text "REV:" at 2379.5,-656.17 h60
  text ".PRJ_Number" at 3224,-656.17 h60
  text "BOARD #:" at 3769.5,-656.17 h60
  text "PCB VIEWED FROM BOTTOM SIDE" at 6246,-656.17 h60
  text "IGNORE ->" at 2547.85,-858.49 h60
  text "TEXAS INSTRUMENTS" at 904.5,-1064.84 h60
  text ".Print_Time" at 2169,-1064.84 h60
  text ".Print_Date" at 2898,-1064.84 h60
  text "GENERATED    :" at 3767.5,-1064.84 h60
  text ".plot_File_Name" at 5440.5,-1064.84 h60
  text "PLOT NAME =" at 6246,-1064.84 h60
M9 Title Sheet:
  drawing of 57 lines, arcs and shapes, not listed
  text "1" at 739.84,8036.5 h70
  text "2" at 3235.5,8036.5 h70
  text "3" at 5724.84,8036.5 h70
  text "4" at 8231.51,8036.5 h70
  text "5" at 10730.5,8036.5 h70
  text "6" at 13235.5,8036.5 h70
  text "A" at -416.5,6893.5 h70
  text "A" at 14383.5,6893.5 h70
  text "B" at -416.5,4513.5 h70
  text "B" at 14383.5,4513.5 h70
  text "C" at -416.5,2138.5 h70
  text "C" at 14383.5,2138.5 h70
  text "PROJECT TITLE:" at 11343.5,277.5 h45
  text ".PRJ_Title" at 11393.5,144.17 h70
  text "DESIGNED FOR:" at 11343.5,-23.5 h45
  text ".PRJ_Customer" at 11393.5,-163.5 h70
  text "D" at -416.5,-231.5 h70
  text "D" at 14383.5,-231.5 h70
  text "FILE NAME:" at 11343.5,-323.5 h45
  text ".PCB_File_Name_No_Path" at 11393.5,-443.5 h70
  text "Texas Instruments (TI) and/or its licensors do not warrant the accuracy or completeness of this specification" at 6374,-605.34 h45
  text "ENGINEER:" at 11343.5,-613.5 h45
  text "LAYOUT BY:" at 12848.5,-613.5 h45
  text "or any information contained therein. TI and/or its licensors do not warrant that this design will meet" at 6329.01,-718 h45
  text ".PRJ_Engineer" at 11393.5,-768.49 h70
  text ".PCB_Layout" at 12899,-768.49 h70
  text "the specifications, will be suitable for your application or fit for any particular purpose, or will operate in" at 6329.01,-830.67 h45
  text ".Layer_Name" at 577,-858.49 h60
  text "ALTIUM DESIGNER VERSION:" at 12848.5,-923.5 h45
  text "an implementation. TI and/or its licensors do not warrant that the design is production worthy. You should" at 6329.01,-943.33 h45
  text "completely validate and test your design implementation to confirm the system functionality for your application." at 6374,-1056 h45
  text ".print_Scale" at 11393.5,-1056.83 h70
  text ".Application_BuildNumber" at 12899,-1056.83 h70
  text "1" at 739.84,-1263.5 h70
  text "2" at 3235.5,-1263.5 h70
  text "3" at 5724.84,-1263.5 h70
  text "4" at 8231.51,-1263.5 h70
  text "5" at 10730.5,-1263.5 h70
  text "6" at 13235.5,-1263.5 h70
M10 Fab Notes:
  drawing of 185 lines, arcs and shapes, not listed
  text "DESIGN INFORMATION" at 12381.02,5910 h60
  text "MIN. TRACK WIDTH:" at 11736.46,5730 h60
  text "8" at 12832.7,5730 h60
  text "MIL" at 12987.46,5730 h60
  text "MIN. CLEARANCE:" at 11736.46,5598 h60
  text "0.2" at 12772.7,5598 h60
  text "mm" at 12987.46,5598 h60
  text "MIN. VIA PAD SIZE:" at 11736.46,5466 h60
  text "20" at 12802.71,5466 h60
  text "MIL" at 12987.46,5466 h60
  text "0.05mm (2MIL)" at 12431.46,5324.29 h60
  text "MINIMUM ANNULAR RING" at 11407.23,5320 h60
  text "EXTERNAL" at 13139.46,5320 h60
  text "PER" at 11607.23,5202 h60
  text "IPC-D-275 CLASS 2 LEVEL C" at 11827.23,5202 h60
  text "MIL, HOLES" at 13315.46,5089.71 h60
  text "+/-" at 12923,5089 h60
  text "+/-" at 13777,5089 h60
  text "REGISTRATION TOLERANCES:" at 11407.23,5084 h60
  text "METAL" at 12607,5084 h60
  text "5" at 13183.2,5084 h60
  text "3" at 14016.2,5084 h60
  text "MIL" at 14132.46,5084 h60
  text "MATERIAL:" at 11332.46,4874.54 h60
  text "FR-4 High Tg" at 12318.9,4734.21 h60
  text "FR-408" at 11753.46,4725.64 h60
  text "OTHER" at 13241.46,4725.64 h60
  text "X" at 12170,4725 h60
  text "62 MIL (1.6mm) +/-10%" at 12073.56,4562.92 h60
  text "THICKNESS:" at 11407.23,4558.64 h60
  text "X" at 11945.4,4558.64 h60
  text "OTHER" at 13358.46,4558.64 h60
  text "TOLERANCE:" at 11407.23,4400.64 h60
  text "X" at 12246.53,4400.64 h60
  text "ANSI IPC-6012 TYPE 3 CLASS 2" at 12433.48,4400.64 h60
  text "OTHER +/-" at 12433.46,4244.64 h60
  text "BOW & TWIST:" at 11407.23,4087.64 h60
  text "X" at 12246.53,4087.64 h60
  text "ANSI IPC-6012 TYPE 3 CLASS 2" at 12433.48,4087.64 h60
  text "OTHER +/-" at 12433.46,3929.13 h60
  text "DRILLING:" at 11332.46,3790.64 h60
  text "REFERENCE:" at 11407.23,3673.64 h60
  text "X" at 12055.46,3673.64 h60
  text "AS SHOWN" at 12242.46,3673.64 h60
  text "X" at 12956.46,3673.64 h60
  text "NC_DRILL FILES" at 13093.46,3673.64 h60
  text "PTH MIN COPPER THICKNESS:" at 11407.23,3515.64 h60
  text "X" at 12757.46,3515.64 h60
  text "1MIL" at 12894.46,3515.64 h60
  text "OTHER" at 13391.46,3515.64 h60
  text "BOARD FINISH:" at 11332.46,3356.64 h60
  text "SILKSCREEN:" at 11487.68,3238.64 h60
  text "X" at 12436.46,3238.64 h60
  text "TOP" at 12562.46,3238.64 h60
  text "X" at 12946.46,3238.64 h60
  text "BOTTOM" at 13073.46,3238.64 h60
  text "SILKSCREEN COLOR:" at 11487.68,3071.64 h60
  text "X" at 12435.42,3071.64 h60
  text "WHITE" at 12562.46,3071.64 h60
  text "OTHER" at 13073.46,3071.64 h60
  text "SOLDER RESIST COLOR:" at 11487.68,2901.64 h60
  text "X" at 12055.42,2742.44 h60
  text "GREEN" at 12182.46,2742.44 h60
  text "BLUE" at 12773.46,2742.44 h60
  text "OTHER" at 13311.46,2742.44 h60
  text "IMMERSION GOLD (ENIG)" at 12393.46,2553.92 h60
  text "ENEPIG" at 13731,2550.64 h60
  text "SURFACE FINISH:" at 11332.46,2549.64 h60
  text "IMM. TIN/SILVER OR EQUIV" at 11662,2392.64 h60
  text "OTHER" at 13093.46,2392.64 h60
  text "X" at 11500,2390 h60
  text "ARRAY/PANEL:" at 11332.46,2213.64 h60
  text "CUT AND TRIM PER MECH LAYER 1" at 12393.46,2209.35 h60
  text "N.C. ROUTE" at 12393.46,2057.64 h60
  text "X" at 13072.46,2057.64 h60
  text "V. SCORE" at 13259.46,2057.64 h60
  text "CERTIFICATION:" at 11332.46,1920.64 h60
  text "MATERIALS AND WORKMANSHIP FOR ALL PCBS" at 12057.46,1920.64 h60
  text "TO MEET OR EXCEED THE REQUIREMENTS OF:" at 12057.46,1822.64 h60
  text "X" at 11683.96,1686.13 h60
  text "ANSI IPC-A-600F CLASS ->" at 11822.96,1686.13 h60
  text "X" at 13462.02,1686.13 h60
  text "2" at 13580.96,1686.14 h60
  text "1" at 13265.96,1684.64 h60
  text "3" at 13934.96,1684.64 h60
  text "X" at 11686.02,1526.64 h60
  text "UL 94V-0" at 11822.96,1526.64 h60
  text "X" at 12498.02,1526.64 h60
  text "RoHS" at 12634.96,1526.64 h60
  text "OTHER" at 13279.36,1526.64 h60
  text "PER ORDER" at 13676.42,1526.64 h60
  text "ADDITIONAL REQUIREMENTS:" at 11332.46,1385.64 h60
  text "MICROSECTION:" at 11407.23,1270.64 h60
  text "YES" at 12312.96,1270.64 h60
  text "REQUIRED" at 13174.46,1114.49 h60
  text "BARE BOARD ELEC. TEST:" at 11407.23,1111.64 h60
  text "NONE" at 12712.96,1111.64 h60
  text "X" at 13047.46,1111.64 h60
  text "PER ORDER" at 13766.46,1111.64 h60
  text "MANUFACTURER'S UL:" at 11407.23,954.64 h60
  text "RAIL" at 12572.96,950.35 h60
  text "METAL" at 13064.77,950.35 h60
  text "X" at 13440,950 h60
  text "SILK" at 13576.46,950.35 h60
  text ".Layer_Name" at 577,-858.49 h60
M11 Gerber Information:
  lines w10: -292,-930.17 6308,-930.17 ; -292,-726.83 6310,-726.83 ; -292,-523.5 -292,-1133.5 3713,-1133.5 6310,-1133.5 6310,-523.5 -291.5,-523.5 -291.5,-1133.5 1284,-1133.5 ; 2173,-1133.5 2173,-523.5 ; 3440,-726.83 3440,-523.5 ; 4280,-726.83 4280,-523.5 ; 4902,-1140 4902,-937.17
  text "ALL ARTWORK VIEWED FROM TOP SIDE" at -228.5,-655.67 h60
  text "BOARD #:" at 2248,-655.67 h60
  text ".PRJ_Number" at 2793.5,-655.67 h60
  text "REV:" at 3638,-655.67 h60
  text ".PCB_Rev" at 3929.5,-655.67 h60
  text "SVN REV:" at 4476,-655.67 h60
  text ".VersionControl_RevNumber" at 4982,-655.67 h60
  text "LAYER NAME =" at -228.5,-858.49 h60
  text "PLOT NAME =" at -228.5,-1064.34 h60
  text ".plot_File_Name" at 577,-1064.34 h60
  text "GENERATED    :" at 2250,-1064.34 h60
  text ".Print_Date" at 3119.5,-1064.34 h60
  text ".Print_Time" at 3848.5,-1064.34 h60
  text "TEXAS INSTRUMENTS" at 5113,-1064.34 h60
M12 Stackup:
  lines w6: 11360,7460 13910,7460 ; 11360,7564.4 13910,7564.4 ; 11300,6975 ccw(c11334,6975) 11334,6941 13936,6941 ccw(c13936,6975) 13970,6975 13970,7681 ccw(c13936,7681) 13936,7715 11334,7715 ccw(c11334,7681) 11300,7681 11300,6975
  text "The Stackup Legend below this is static." at 11605.5,7874.5 h60
  text "If you change the stackup, update the Legend." at 11615.5,7784.5 h60
  text "Layer Stack Up Detail for: Ref_Design.PcbDoc" at 11360,7597.1 h57
  text "Layer" at 11360,7525.4 h24
  text "Gerber" at 12255.81,7525.4 h24
  text "Copper" at 12819.33,7525.4 h24
  text "Dielectric" at 13422.04,7525.4 h24
  text "Name" at 11360,7477.4 h24
  text "Document" at 12255.81,7477.4 h24
  text "Thickness" at 12819.33,7477.4 h24
  text "Material" at 13422.04,7477.4 h24
  text "Top Solder Mask" at 11360,7384.44 h34
  text "(.GTS)" at 12255.81,7384.44 h34
  text "Solder Resist" at 13422.04,7384.44 h34
  text "Top Layer" at 11360,7287.69 h34
  text "(.GTL)" at 12255.81,7287.69 h34
  text "2.8mil" at 12819.33,7287.69 h34
  text "FR-4" at 13422.04,7239.31 h34
  text "Bottom Layer" at 11360,7190.94 h34
  text "(.GBL)" at 12255.81,7190.94 h34
  text "2.8mil" at 12819.33,7190.94 h34
  text "Bottom Solder Mask" at 11360,7094.19 h34
  text "(.GBS)" at 12255.81,7094.19 h34
  text "Solder Resist" at 13422.04,7094.19 h34
  text ".Layer_Name" at 577,-858.49 h60
M13 Component Bodies Top:
  text ".Layer_Name" at 577,-858.49 h60
M14 Component Bodies Bottom:
  text ".Layer_Name" at 577,-858.49 h60
M15 Courtyards Top:
  text ".Layer_Name" at 577,-858.49 h60
M16 Courtyards Bottom:
  text ".Layer_Name" at 577,-858.49 h60
Drill Drawing:
  text ".legend" at 5122.5,725.5 h60
  text "Drill Table" at 5147.5,540.5 h60
  text ".Layer_Name" at 577,-858.49 h60

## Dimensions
0,-410.5 to 1000,-410.5 on M2 Board Dimensions
0,0 to 1968.5,0 on M2 Board Dimensions
0,0 to 0,590.55 on M2 Board Dimensions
